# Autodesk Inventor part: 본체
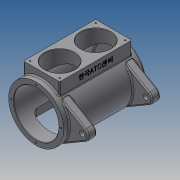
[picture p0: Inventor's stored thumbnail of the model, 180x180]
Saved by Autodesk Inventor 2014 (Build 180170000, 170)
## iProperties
Created: 2016-11
Part Number: 본체
Material: 알루미늄 6061
Document SubType Name: Modeling
Designer: mduedu
Density: 2.71 g/cm^3
Mass: 2578.2 g
Surface Area: 1746.63 cm^2
Volume: 951.364 cm^3
Appearance: 기본값
Author: mduedu
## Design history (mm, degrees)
sketch "스케치1"
  geometry: C1 r 65 at (0, 0); 1 further point
  constraints: 1 centre point, 1 coincident
  dimensions: "d119" = 130 diameter of C1
extrude "돌출1" new body sketch "스케치1" distance "d3" = 98; taper "d4" = 0 deg; dims "d132" = 97, "d133" = 0
feature "쉘1" dims "d120" = 12, "d134" = 8
node "작업 평면2"
sketch "스케치13"
  geometry: L1 (42.5, 85)-(-42.5, 85); L2 (-42.5, 85)-(-42.5, -85); L3 (-42.5, -85)-(42.5, -85); L4 (42.5, -85)-(42.5, 85); 2 further points
  constraints: 8 end point, 2 parallel, 1 horizontal, 1 midpoint, 1 perpendicular, 1 vertical alignment
  dimensions: "d122" = 170 distance of L1.end L2.end; "d124" = 85 distance of L2.end L3.end; "d125" = 85 distance from line of point (0, 0) L1 (= 0.5 x d122)
extrude "돌출11" join sketch "스케치13" stored distance "d126" = 10; taper "d127" = 0 deg
sketch "스케치14"
  geometry: L1 (65, 97)-(-65, 97) reference; C1 r 35 at (0, 42.5); 1 further point
  constraints: 1 centre point, 1 vertical alignment
  dimensions: "d128" = 70 diameter of C1; "d129" = 54.5 distance from line of C1.centre L1
extrude "돌출12" cut sketch "스케치14" stored distance "d130" = 10; taper "d131" = 0 deg
sketch "스케치15"
  geometry: C1 r 53 at (0, 0) reference; 1 further point
extrude "돌출13" cut sketch "스케치15" stored distance "d135" = 10; taper "d136" = 0 deg
chamfer "모따기1" distance "d54" = 1; stored, may be unused: second distance "d55" = 2, angle "d56" = 45 deg
sketch "스케치8"
  geometry: C1 r 23 at (0, 0); C2 r 65 at (0, 0) reference; 1 further point
  constraints: 1 centre point, 1 concentric
  dimensions: "d57" = 46 diameter of C1
extrude "돌출8" join sketch "스케치8" distance "d58" = 14; taper "d59" = 0 deg
feature "면 기울기1" dims angle "d202" = 10 deg
hole "구멍3" diameter "d62" = 24; stored, may be unused: countersink angle "d66" = 90 deg, drill point angle "d68" = 0 deg; dims "d63" = 6, "d64" = 28, "d65" = 8, "d67" = 14, "d169" = 10, "d170" = 10
fillet "모깎기11" dims "d69" = 3
fillet "모깎기12" dims "d70" = 3
fillet "모깎기13" dims "d71" = 0.3
chamfer "모따기2" distance "d72" = 1; stored, may be unused: second distance "d73" = 2, angle "d74" = 45 deg
node "작업 평면3"
sketch "스케치16"
  geometry: L1 (-42.5, -80)-(52.5, -80); L2 (-42.5, -80)-(24.675, -12.825); L3 (-42.5, -80)-(24.675, -147.175); L4 (3.462, -34.038)-(60.057, -67.042); L5 (3.462, -125.962)-(60.057, -92.958); A1 r 65 centre (-42.5, -80) between (3.462, -34.038) and (3.462, -125.962) reference; A2 r 65 centre (-42.5, -80) between (3.462, -125.962) and (3.462, -34.038); A3 r 95 centre (-42.5, -80) between (52.5, -80) and (24.675, -147.175); A4 r 15 centre (52.5, -80) between (60.057, -67.042) and (60.057, -92.958); 1 further point
  constraints: 10 end point, 9 point on circle, 3 centre point, 3 coincident, 2 point on line, 2 tangent, 1 horizontal
  dimensions: "d140" = 45 deg angle of L3 L1; "d141" = 45 deg angle of L2 L1; "d194" = 30 radial gap between concentric circles of A3 A1; "d195" = 30 diameter of A4
extrude "돌출14" join sketch "스케치16" distance "d143" = 20; taper "d144" = 0 deg
fillet "모깎기25" dims "d196" = 3
fillet "모깎기26" dims "d197" = 3
sketch "스케치22"
  geometry: C1 r 6 at (52.5, -80); A1 r 15 centre (52.5, -80) between (60.057, -92.958) and (60.057, -67.042) reference; 1 further point
  constraints: 1 centre point, 1 coincident
  dimensions: "d198" = 12 diameter of C1
extrude "돌출17" cut sketch "스케치22" stored distance "d200" = 10; taper "d201" = 0 deg
fillet "모깎기20" dims "d159" = 3
fillet "모깎기21" dims "d160" = 3
fillet "모깎기22" dims "d161" = 3
node "작업 평면4"
sketch "스케치18"
  geometry: L1 (-42.5, 65)-(42.5, 65); L2 (42.5, 65)-(42.5, -65); L3 (42.5, -65)-(-42.5, -65); L4 (-42.5, -65)-(-42.5, 65); 2 further points
  constraints: 8 end point, 2 parallel, 1 horizontal, 1 midpoint, 1 perpendicular, 1 vertical alignment
  dimensions: "d162" = 130 distance of L1.end L2.end; "d164" = 85 distance of L2.end L3.end; "d165" = 65 distance from line of point (0, 0) L1 (= 0.5 x d162)
extrude "돌출16" cut sketch "스케치18" stored distance "d166" = 15; taper "d167" = 0 deg
fillet "모깎기23" dims "d168" = 10
fillet "모깎기24" dims "d173" = 3
sketch "스케치19"
  geometry: 4 further points
  constraints: 4 other
hole "구멍6" sketch "스케치19" at (0, -59), (59, 0), (-59, 0), (0, 59) diameter "d174" = 3.242; stored, may be unused: countersink angle "d178" = 90 deg, drill point angle "d180" = 120 deg; dims "d175" = 7, "d176" = 4, "d177" = 2, "d179" = 9
sketch "스케치20"
  geometry: L1 (35, -77.5)-(-35, -77.5); L2 (-35, -77.5)-(-35, -7.5); L3 (-35, -7.5)-(35, -7.5); L4 (35, -7.5)-(35, -77.5); L5 (35, -77.5)-(-35, -7.5); L6 (-35, -77.5)-(35, -7.5); C1 r 36 at (0, -42.5) reference; 3 further points
  constraints: 12 end point, 2 coincident, 2 midpoint, 2 parallel, 1 horizontal, 1 perpendicular
  dimensions: "d181" = 70 distance of L2.end L3.end; "d182" = 70 distance of L1.end L2.end
hole "구멍7" sketch "스케치20" at (-35, -77.5), (35, -77.5) diameter "d183" = 3.242; stored, may be unused: countersink angle "d187" = 90 deg, drill point angle "d189" = 118 deg; dims "d184" = 7, "d185" = 4, "d186" = 2, "d188" = 9
sketch "스케치21"
  geometry: L1 (164, 0)-(0, 0) reference; L2 (-3, 0)-(-3, -24.649) reference; 3 further points
  constraints: 1 midpoint, 1 vertical alignment, 1 other
  dimensions: "d190" = 15 distance from line of point (82, -15) L1; "d191" = 85 distance from line of point (82, 0) L2 (derived)
feature "엠보싱2" sketch "스케치21" dims "d119" = 130, "d192" = 0.5, "d193" = 0
node "솔리드1"
mirror "대칭5"
mirror "대칭6"
mirror "대칭7"
